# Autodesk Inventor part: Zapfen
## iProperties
Shininess: 64.0
Length Units: 11269
Angle Units: 11279
Time Units: 11290
Mass Units: 11283
Length Display Precision: 3
Angle Display Precision: 2
Compacted: True
Part Number: Zapfen
Document SubType Name: Modeling
Created: 2004-05
Material: Standard
Designer: KWU_CAD
Manufacturer: Standard
Standards Organization: Custom
Density: 0.0
Volumn: 0.0
Area: 0.0
PropertySet Name: Model Information
Control State: 0
Master: False
Checked Out: False
Author: KWU_CAD
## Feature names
1. Drehung1 [Revolution]
